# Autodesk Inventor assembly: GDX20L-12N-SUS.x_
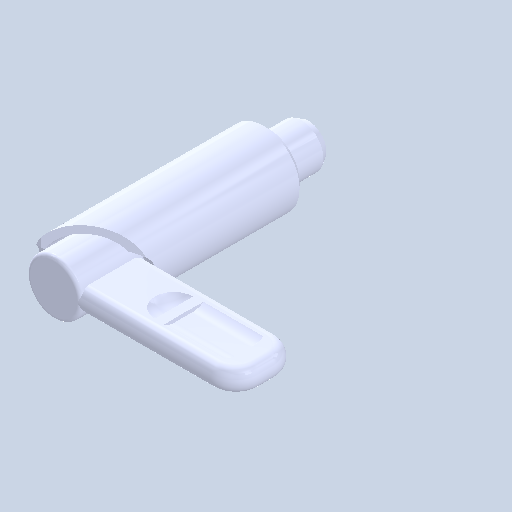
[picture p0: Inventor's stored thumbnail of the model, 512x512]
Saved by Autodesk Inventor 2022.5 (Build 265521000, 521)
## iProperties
Created: 2024-06
Part Number: GDX20L-12N-SUS.x_
Document SubType Name: Assembly
Designer: ImaoCorp
Author: ImaoCorp
Sending System: SOLIDWORKS 2022-2022290
MC: AMD64
MC_MODEL: Intel64 Family 6 Model 60 Stepping 3, GenuineIntel
OS: Windows_NT
FRU: Parasolid Version 33.1, build 260,  4-25-2022
FORMAT: text
GUISE: transmit
KEY: FILEGDX20L-12N-SUS.x_t
DATE: Wed Jun 12 09:32:51 2024
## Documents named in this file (3)
- Y:\5.更新分\2024年対応\xxxx_GDX\データ_imao品番\gdx20l-12n-sus\GDX20L-12N-SUS.x_.iam
- Y:\5.更新分\2024年対応\xxxx_GDX\データ_imao品番\gdx20l-12n-sus\GDX20L-12N-SUS_01.ipt
- Y:\5.更新分\2024年対応\xxxx_GDX\データ_imao品番\gdx20l-12n-sus\GDX20L-12N-SUS_02.ipt
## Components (2 placed, 2 different names)
1. GDX20L-12N-SUS_01
2. GDX20L-12N-SUS_02
